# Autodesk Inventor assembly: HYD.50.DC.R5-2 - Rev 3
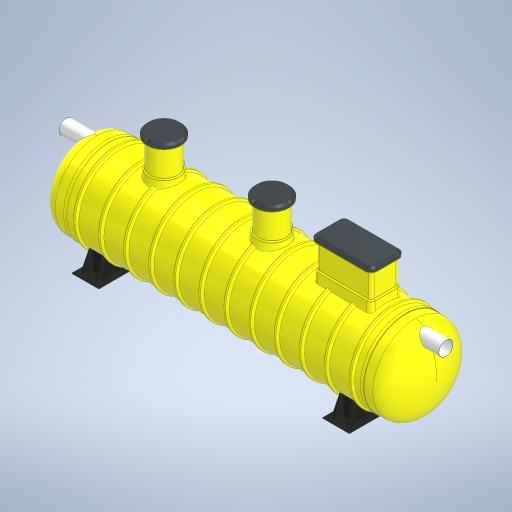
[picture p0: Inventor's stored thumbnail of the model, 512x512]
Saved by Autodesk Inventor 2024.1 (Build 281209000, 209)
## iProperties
Created: 2023-08
Part Number: HYD.50.DC.R5-2 - Rev 3
Document SubType Name: Assembly
Designer: macga
Author: macga
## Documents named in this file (43)
- D:\$ Protector Vault\Workspace\Automation Files\1. Protector Stardard Products\HydroProtectors\FAMILY\HYD.50 - Vernon\HYD.50.DC.R5-2 - Rev 3.iam
- D:\$ Protector Vault\Workspace\1. Protector Stardard Products\HydroProtectors\FAMILY\HORIZONTAL TANK - IPART\HORIZONTAL TANK - IPART\WIN.HB.1850x6650L-9.ipt
- D:\$ Protector Vault\Workspace\1. Protector Stardard Products\HydroProtectors\FAMILY\HORIZONTAL TANK - IPART\HORIZONTAL TANK - IPART.ipt
- D:\$ Protector Vault\Workspace\1. Protector Stardard Products\HydroProtectors\FAMILY\DOME - IPART\DOME - IPART\SU.DOME.1850-9.ipt
- D:\$ Protector Vault\Workspace\1. Protector Stardard Products\HydroProtectors\FAMILY\DOME - IPART\DOME - IPART.ipt
- D:\$ Protector Vault\Workspace\1. Protector Stardard Products\HydroProtectors\FAMILY\FOOT - IPART\FRP Foot - IPART\SU.HS.FOOT.1850.ipt
- D:\$ Protector Vault\Workspace\1. Protector Stardard Products\HydroProtectors\FAMILY\FOOT - IPART\FRP Foot - IPART.ipt
- D:\$ Protector Vault\Workspace\1. Protector Stardard Products\HydroProtectors\FAMILY\HYD.BAFFLE - IPART\SU.BAFFLE.1850\SU.BAFFLE.1850.ipt
- D:\$ Protector Vault\Workspace\1. Protector Stardard Products\HydroProtectors\FAMILY\HYD.BAFFLE - IPART\SU.BAFFLE.1850.ipt
- D:\$ Protector Vault\Workspace\1. Protector Stardard Products\HydroProtectors\FAMILY\ACD Base - IPART\SU.ACDBASE.1850\SU.ACDBASE.1850-300ACDFV.ipt
- D:\$ Protector Vault\Workspace\1. Protector Stardard Products\HydroProtectors\FAMILY\ACD Base - IPART\SU.ACDBASE.1850.ipt
- D:\$ Protector Vault\Workspace\1. Protector Stardard Products\HydroProtectors\FAMILY\ACDTUBE - IPART\ACDTUBE - IPART\ACDTUBE.300-1880.ipt
- D:\$ Protector Vault\Workspace\1. Protector Stardard Products\HydroProtectors\FAMILY\ACDTUBE - IPART\ACDTUBE - IPART.ipt
- D:\$ Protector Vault\Workspace\1. Protector Stardard Products\HydroProtectors\FAMILY\ACD FLOAT VALVE - IPART\ACD.FloatValve - IASSY\ACD.FVALVE.300.ASSY.iam
- D:\$ Protector Vault\Workspace\1. Protector Stardard Products\HydroProtectors\FAMILY\ACD FLOAT VALVE - IPART\ACD.FloatValve - IASSY.iam
- D:\$ Protector Vault\Workspace\Automation Files\1. Protector Stardard Products\HydroProtectors\FAMILY\CF.BASE - IPART\CF BASE DUAL - IPART\SU.CFBASE1.1850.DUAL\SU.CFBASE1.1850.DUAL-R5.300-OP.ipt
- D:\$ Protector Vault\Workspace\Automation Files\1. Protector Stardard Products\HydroProtectors\FAMILY\CF.BASE - IPART\CF BASE DUAL - IPART\SU.CFBASE1.1850.DUAL.ipt
- D:\$ Protector Vault\Workspace\1. Protector Stardard Products\HydroProtectors\FAMILY\COALESCER FILTER - IPART\CF-R5.iam
- D:\$ Protector Vault\Workspace\1. Protector Stardard Products\HydroProtectors\FAMILY\SU.600Dia Manway Adaptor - IPART\Horizontal 600mmDia Manway Adaptor (FLANGED) SU.MWA.HS.6R-1850-1850\SU.MWA.HS.6R-1850.ipt
- D:\$ Protector Vault\Workspace\1. Protector Stardard Products\HydroProtectors\FAMILY\SU.600Dia Manway Adaptor - IPART\SU.MWA.HS.6R - IPART.ipt
- D:\$ Protector Vault\Workspace\1. Protector Stardard Products\HydroProtectors\FAMILY\WIN.600mmDiaManwayRiser - IPART\600mmDia Manway Riser.ipt
- D:\$ Protector Vault\Workspace\1. Protector Stardard Products\HydroProtectors\Automation Files\600mmDia Manway Cover.ipt
- D:\$ Protector Vault\Workspace\1. Protector Stardard Products\HydroProtectors\HYD.50 300 Outlet Vertical.ipt
- D:\$ Protector Vault\Workspace\1. Protector Stardard Products\HydroProtectors\FAMILY\OUTLET ELBOW - IPART\OUTLET ELBOW - IPART.ipt
- D:\$ Protector Vault\Workspace\1. Protector Stardard Products\HydroProtectors\FAMILY\600x1200mm Manway Adaptor - IPART\600x1200mm Manway Adaptor - IPART\SU.MRADAPTOR.1850.600Lx1200W.ipt
- D:\$ Protector Vault\Workspace\1. Protector Stardard Products\HydroProtectors\FAMILY\600x1200mm Manway Adaptor - IPART\600x1200mm Manway Adaptor - IPART.ipt
- D:\$ Protector Vault\Workspace\1. Protector Stardard Products\HydroProtectors\Coalescer Guide Rail.ipt
- D:\$ Protector Vault\Workspace\1. Protector Stardard Products\HydroProtectors\ISO 4065 Pipe DN315x2.5xS63 - 1365.ipt
- D:\$ Protector Vault\Workspace\1. Protector Stardard Products\HydroProtectors\FAMILY\INLET PIPE ELBOW- IPART\INLET PIPE ELBOW- IPART\InletPipeElbow.300D.ipt
- D:\$ Protector Vault\Workspace\1. Protector Stardard Products\HydroProtectors\FAMILY\INLET PIPE ELBOW- IPART\INLET PIPE ELBOW- IPART.ipt
- D:\$ Protector Vault\Workspace\1. Protector Stardard Products\HydroProtectors\Automation Files\Access Risers\600x1200 Manway Riser.ipt
- D:\$ Protector Vault\Workspace\1. Protector Stardard Products\HydroProtectors\Automation Files\Access Risers\600x 1200mm Manway Cover.ipt
- D:\$ Protector Vault\Workspace\1. Protector Stardard Products\HydroProtectors\Upper Guide Rai Braket.ipt
- D:\$ Protector Vault\Workspace\1. Protector Stardard Products\Standard Components\Flanged Vent.ipt
- D:\$ Protector Vault\Workspace\1. Protector Stardard Products\HydroProtectors\HYD Oil Probe\Oil Probe Assembly.iam
- D:\$ Protector Vault\Workspace\1. Protector Stardard Products\Xtremeprotector\Vault\Chain.ipt
- D:\$ Protector Vault\Workspace\1. Protector Stardard Products\Xtremeprotector\Vault\Lifting Eye.ipt
- D:\$ Protector Vault\Workspace\1. Protector Stardard Products\HydroProtectors\FAMILY\OUTLET ELBOW - IPART\OUTLET ELBOW - IPART\OutletPipeElbow.300D-100DCoupling.ipt
- D:\$ Protector Vault\Workspace\1. Protector Stardard Products\Xtremeprotector\Vault\Chain\Chain-01.ipt
- D:\$ Protector Vault\Workspace\1. Protector Stardard Products\HydroProtectors\FAMILY\WIN.600mmDiaManwayRiser - IPART\600mmDia Manway Riser\SU.600mmDia.ManwayRiser.600-10.ipt
- D:\$ Protector Vault\Workspace\1. Protector Stardard Products\HydroProtectors\FAMILY\Coalescer Guide Rail-014.ipt
- D:\$ Protector Vault\Workspace\1. Protector Stardard Products\HydroProtectors\FAMILY\Coalescer Guide Rail-015.ipt
- D:\$ Protector Vault\Workspace\1. Protector Stardard Products\Trade Waste Sampling Point Assembly 300.iam
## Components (39 placed, 27 different names)
1. WIN.HB.1850x6650L-9:1
2. SU.DOME.1850-9:1 — Mate:1, Mate:3, Mate:10, Mate:82
3. SU.DOME.1850-9:2 — Mate:2, Mate:4, Mate:17, Angle:4
4. SU.HS.FOOT.1850:1 — Mate:5, Mate:6
5. SU.HS.FOOT.1850:2 — Mate:7, Mate:8
6. SU.BAFFLE.1850:1 — Mate:9, Mate:10, Mate:12
7. SU.ACDBASE.1850-300ACDFV:1 — Mate:11, Mate:12, Mate:13, Mate:14
8. ACDTUBE.300-1880:1 — Mate:13, Mate:14, Mate:15, Mate:38, Mate:42
9. ACD.FVALVE.300.ASSY:1 [sub-assembly] — Mate:15
10. SU.CFBASE1.1850.DUAL-R5.300-OP:1
11. CF-R5:1 [sub-assembly] — Mate:18, Mate:19
12. CF-R5:2 [sub-assembly] — Mate:20, Mate:21, Mate:83
13. SU.600mmDia.ManwayRiser.600-10:1 — Mate:30, Mate:31, Mate:40, Mate:41, Flush:2
14. SU.600mmDia.ManwayRiser.600-10:2 — Mate:32, Mate:33, Mate:44, Mate:45
15. 600mmDia Manway Cover:1 — Mate:32, Mate:33
16. 600mmDia Manway Cover:2 — Mate:30, Mate:31, Angle:2
17. HYD.50 300 Outlet Vertical:1 — Mate:34, Mate:35, Mate:36, Mate:37
18. OutletPipeElbow.300D-100DCoupling:2 — Mate:36, Mate:37, Mate:53, Mate:54, Angle:4
19. SU.MWA.HS.6R-1850:2 — Mate:38, Mate:39, Mate:40, Mate:41, Mate:68, Mate:69, Tangent:2
20. SU.MWA.HS.6R-1850:3 — Mate:42, Mate:43, Mate:44, Mate:45, Mate:66, Mate:73, Flush:8, Mate:74
21. Coalescer Guide Rail-014:1 — Mate:47, Mate:48, Mate:49, Mate:62, Mate:63, Flush:5
22. Coalescer Guide Rail-015:2 — Mate:50, Mate:51, Mate:52, Mate:64, Mate:65, Flush:6
23. ISO 4065 Pipe DN315x2.5xS63 - 1365:2 — Mate:82
24. ISO 4065 Pipe DN315x2.5xS63 - 1365:1 — Mate:53, Mate:54, Mate:87, Mate:88
25. InletPipeElbow.300D:1
26. 600x1200 Manway Riser:1 — Flush:2, Mate:61, Flush:3, Flush:4, Mate:79, Flush:10, Flush:11, Mate:84
27. 600x 1200mm Manway Cover:1 — Mate:61, Flush:3, Flush:4, Angle:1
28. Upper Guide Rai Braket:1 — Mate:62, Mate:63, Flush:5
29. Upper Guide Rai Braket:2 — Mate:64, Mate:65, Flush:6
30. Flanged Vent:1 — Mate:66, Mate:74
31. Flanged Vent:2 — Mate:68, Mate:69
32. Flanged Vent:3 — Mate:71, Mate:75
33. SU.MRADAPTOR.1850.600Lx1200W:1 — Mate:70, Flush:7, Mate:71, Tangent:1, Mate:75, Flush:10, Flush:11
34. Oil Probe Assembly:1 [sub-assembly] — Mate:73, Flush:8, Angle:3, Mate:86
35. Chain-01:3 — Mate:83, Mate:85
36. Chain-01:4 — Mate:80
37. Lifting Eye:1 — Mate:79, Mate:80
38. Lifting Eye:2 — Mate:84, Mate:85
39. Trade Waste Sampling Point Assembly 300:1 [sub-assembly] — Mate:87, Mate:88
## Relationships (81: Mate 66, Flush 9, Angle 4, Tangent 2)
- Mate:1: SU.DOME.1850-9:1
- Mate:2: SU.DOME.1850-9:2
- Mate:3: SU.DOME.1850-9:1
- Mate:4: SU.DOME.1850-9:2
- Mate:5: SU.HS.FOOT.1850:1
- Mate:6: SU.HS.FOOT.1850:1
- Mate:7: SU.HS.FOOT.1850:2
- Mate:8: SU.HS.FOOT.1850:2
- Mate:9: SU.BAFFLE.1850:1
- Mate:10: SU.DOME.1850-9:1 ↔ SU.BAFFLE.1850:1
- Mate:11: SU.ACDBASE.1850-300ACDFV:1
- Mate:12: SU.BAFFLE.1850:1 ↔ SU.ACDBASE.1850-300ACDFV:1
- Mate:13: SU.ACDBASE.1850-300ACDFV:1 ↔ ACDTUBE.300-1880:1
- Mate:14: SU.ACDBASE.1850-300ACDFV:1 ↔ ACDTUBE.300-1880:1
- Mate:15: ACDTUBE.300-1880:1 ↔ ACD.FVALVE.300.ASSY:1
- Mate:17: SU.DOME.1850-9:2
- Mate:18: CF-R5:1
- Mate:19: CF-R5:1
- Mate:20: CF-R5:2
- Mate:21: CF-R5:2
- Mate:30: SU.600mmDia.ManwayRiser.600-10:1 ↔ 600mmDia Manway Cover:2
- Mate:31: SU.600mmDia.ManwayRiser.600-10:1 ↔ 600mmDia Manway Cover:2
- Mate:32: SU.600mmDia.ManwayRiser.600-10:2 ↔ 600mmDia Manway Cover:1
- Mate:33: SU.600mmDia.ManwayRiser.600-10:2 ↔ 600mmDia Manway Cover:1
- Mate:34: HYD.50 300 Outlet Vertical:1
- Mate:35: HYD.50 300 Outlet Vertical:1
- Mate:36: HYD.50 300 Outlet Vertical:1 ↔ OutletPipeElbow.300D-100DCoupling:2
- Mate:37: HYD.50 300 Outlet Vertical:1 ↔ OutletPipeElbow.300D-100DCoupling:2
- Mate:38: ACDTUBE.300-1880:1 ↔ SU.MWA.HS.6R-1850:2
- Mate:39: SU.MWA.HS.6R-1850:2
- Mate:40: SU.600mmDia.ManwayRiser.600-10:1 ↔ SU.MWA.HS.6R-1850:2
- Mate:41: SU.600mmDia.ManwayRiser.600-10:1 ↔ SU.MWA.HS.6R-1850:2
- Mate:42: ACDTUBE.300-1880:1 ↔ SU.MWA.HS.6R-1850:3
- Mate:43: SU.MWA.HS.6R-1850:3
- Mate:44: SU.600mmDia.ManwayRiser.600-10:2 ↔ SU.MWA.HS.6R-1850:3
- Mate:45: SU.600mmDia.ManwayRiser.600-10:2 ↔ SU.MWA.HS.6R-1850:3
- Mate:47: Coalescer Guide Rail-014:1
- Mate:48: Coalescer Guide Rail-014:1
- Mate:49: Coalescer Guide Rail-014:1
- Mate:50: Coalescer Guide Rail-015:2
- Mate:51: Coalescer Guide Rail-015:2
- Mate:52: Coalescer Guide Rail-015:2
- Mate:53: OutletPipeElbow.300D-100DCoupling:2 ↔ ISO 4065 Pipe DN315x2.5xS63 - 1365:1
- Mate:54: OutletPipeElbow.300D-100DCoupling:2 ↔ ISO 4065 Pipe DN315x2.5xS63 - 1365:1
- Flush:2: SU.600mmDia.ManwayRiser.600-10:1 ↔ 600x1200 Manway Riser:1
- Mate:61: 600x1200 Manway Riser:1 ↔ 600x 1200mm Manway Cover:1
- Flush:3: 600x1200 Manway Riser:1 ↔ 600x 1200mm Manway Cover:1
- Flush:4: 600x1200 Manway Riser:1 ↔ 600x 1200mm Manway Cover:1
- Mate:62: Coalescer Guide Rail-014:1 ↔ Upper Guide Rai Braket:1
- Mate:63: Coalescer Guide Rail-014:1 ↔ Upper Guide Rai Braket:1
- Flush:5: Coalescer Guide Rail-014:1 ↔ Upper Guide Rai Braket:1
- Mate:64: Coalescer Guide Rail-015:2 ↔ Upper Guide Rai Braket:2
- Mate:65: Coalescer Guide Rail-015:2 ↔ Upper Guide Rai Braket:2
- Flush:6: Coalescer Guide Rail-015:2 ↔ Upper Guide Rai Braket:2
- Mate:66: SU.MWA.HS.6R-1850:3 ↔ Flanged Vent:1
- Mate:68: SU.MWA.HS.6R-1850:2 ↔ Flanged Vent:2
- Mate:69: SU.MWA.HS.6R-1850:2 ↔ Flanged Vent:2
- Mate:70: SU.MRADAPTOR.1850.600Lx1200W:1
- Flush:7: SU.MRADAPTOR.1850.600Lx1200W:1
- Mate:71: Flanged Vent:3 ↔ SU.MRADAPTOR.1850.600Lx1200W:1
- Angle:1: 600x 1200mm Manway Cover:1
- Tangent:1: SU.MRADAPTOR.1850.600Lx1200W:1
- Angle:2: 600mmDia Manway Cover:2
- Tangent:2: SU.MWA.HS.6R-1850:2
- Mate:73: SU.MWA.HS.6R-1850:3 ↔ Oil Probe Assembly:1
- Flush:8: SU.MWA.HS.6R-1850:3 ↔ Oil Probe Assembly:1
- Mate:74: SU.MWA.HS.6R-1850:3 ↔ Flanged Vent:1
- Mate:75: Flanged Vent:3 ↔ SU.MRADAPTOR.1850.600Lx1200W:1
- Mate:79: 600x1200 Manway Riser:1 ↔ Lifting Eye:1
- Mate:80: Chain-01:4 ↔ Lifting Eye:1
- Flush:10: 600x1200 Manway Riser:1 ↔ SU.MRADAPTOR.1850.600Lx1200W:1
- Mate:82: SU.DOME.1850-9:1 ↔ ISO 4065 Pipe DN315x2.5xS63 - 1365:2
- Angle:3: Oil Probe Assembly:1
- Flush:11: 600x1200 Manway Riser:1 ↔ SU.MRADAPTOR.1850.600Lx1200W:1
- Angle:4: SU.DOME.1850-9:2 ↔ OutletPipeElbow.300D-100DCoupling:2
- Mate:83: CF-R5:2 ↔ Chain-01:3
- Mate:84: 600x1200 Manway Riser:1 ↔ Lifting Eye:2
- Mate:85: Chain-01:3 ↔ Lifting Eye:2
- Mate:86: Oil Probe Assembly:1
- Mate:87: ISO 4065 Pipe DN315x2.5xS63 - 1365:1 ↔ Trade Waste Sampling Point Assembly 300:1
- Mate:88: ISO 4065 Pipe DN315x2.5xS63 - 1365:1 ↔ Trade Waste Sampling Point Assembly 300:1
